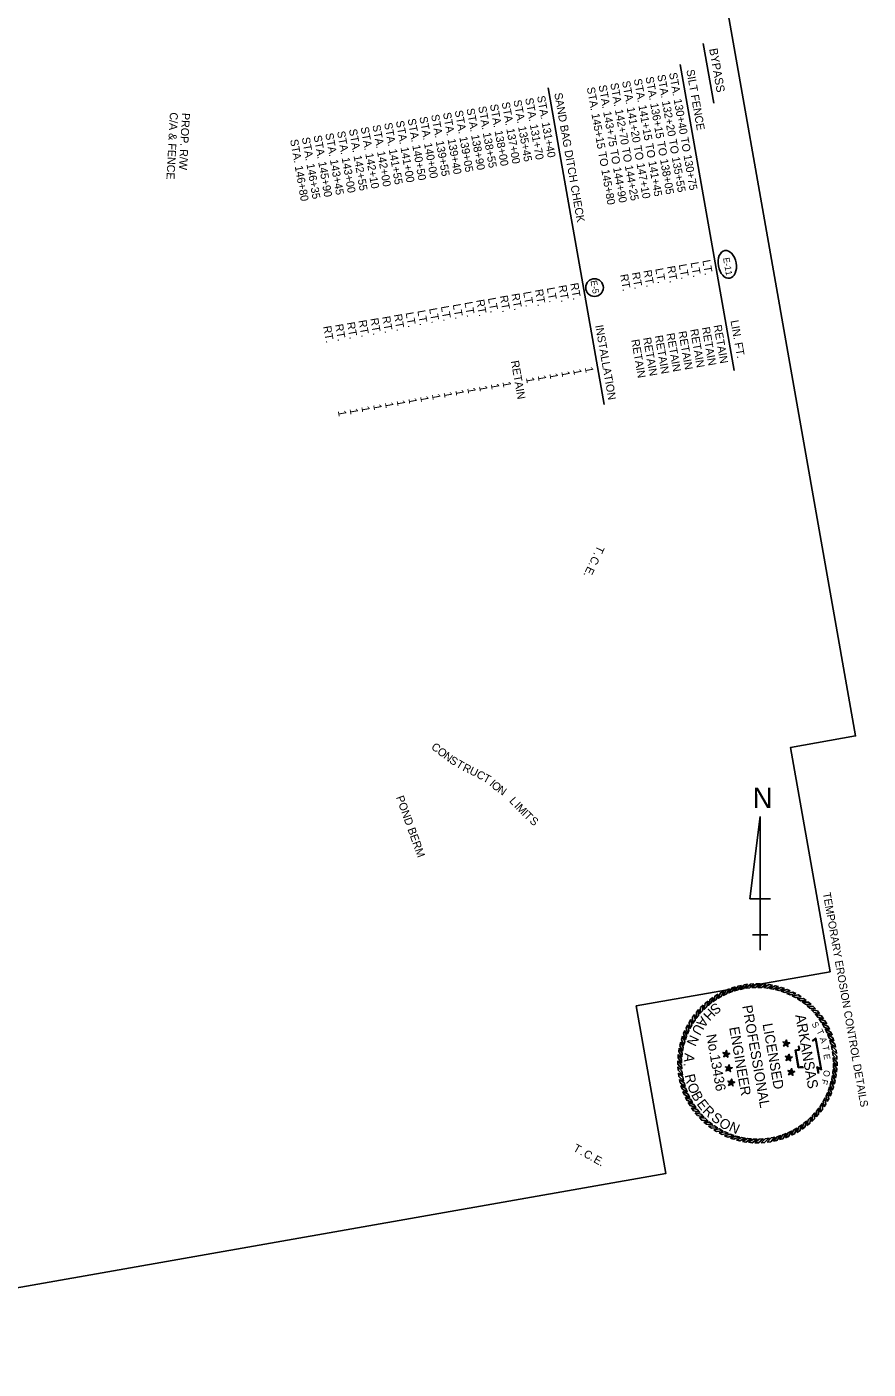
# Model space of a CAD drawing. Extents: x 979945 to 981206, y 1838799 to 1840551.
# Drawn here: x 980575 to 981206, y 1838799 to 1839805 of the extents above; entities that cross this region are included whole.
import ezdxf

# ---------------------------------------------------------------- set-up
doc = ezdxf.new("R2010")
doc.units = 0
for name, color, linetype in [('1', 7, 'Continuous'), ('44', 7, 'Continuous'), ('63', 7, 'Continuous'), ('Default', 7, 'Continuous'), ('G-ANNO-SYMB', 7, 'Continuous'), ('R_Draft', 7, 'Continuous')]:
    doc.layers.add(name, color=color, linetype=linetype)

msp = doc.modelspace()

# ---------------------------------------------------------------- linework, layer by layer
at = {"layer": '1'}
msp.add_circle((981000.5, 1839609.8), 6.61, dxfattribs=at)
msp.add_ellipse((981100, 1839627.2), major_axis=(1.8, -10.4), ratio=0.638788, dxfattribs=at)
at = {"layer": '44'}
for p, q in [((981081.9, 1839792.9), (981089.8, 1839748)), ((981064.8, 1839777), (981105.2, 1839547.7)), ((980965.8, 1839759.5), (981007.6, 1839522.2))]:
    msp.add_line(p, q, dxfattribs=at)
at = {"layer": '63'}
for p, q in [((981124.6, 1839213.1), (981116.9, 1839151.5)), ((981124.6, 1839113.1), (981124.6, 1839213.1)), ((981124.6, 1839213.1), (981124.6, 1839136.2)), ((981116.9, 1839151.5), (981132.3, 1839151.5)), ((981124.6, 1839113.1), (981124.6, 1839136.2)), ((981124.6, 1839124.6), (981118.8, 1839124.6)), ((981118.8, 1839124.6), (981130.4, 1839124.6)), ((981124.6, 1839113.1), (981124.6, 1839124.6))]:
    msp.add_line(p, q, dxfattribs=at)
at = {"layer": 'Default'}
msp.add_lwpolyline([(979944.5, 1840369.9), (980971, 1840550.9), (981196.2, 1839273.6), (981147.4, 1839265), (981177.1, 1839096.8), (981031.8, 1839071.2), (981054, 1838945.6), (980221.5, 1838798.8)], close=True, dxfattribs=at)
at = {"layer": 'G-ANNO-SYMB'}
for points in [[(981101.6, 1839084), (981099.2, 1839083), (981097, 1839079), (981099.5, 1839080.2)], [(981106.1, 1839085.5), (981103.6, 1839084.7), (981101.1, 1839080.9), (981103.7, 1839081.9)], [(981110.6, 1839086.6), (981108.1, 1839086), (981105.3, 1839082.4), (981108, 1839083.2)], [(981115.2, 1839087.4), (981112.7, 1839087), (981109.6, 1839083.6), (981112.3, 1839084.2)], [(981119.9, 1839087.8), (981117.3, 1839087.6), (981114, 1839084.4), (981116.8, 1839084.8)], [(981124.6, 1839087.8), (981122, 1839087.8), (981118.5, 1839084.9), (981121.2, 1839085.1)], [(981129.2, 1839087.5), (981126.7, 1839087.7), (981122.9, 1839085.1), (981125.7, 1839085)], [(981133.9, 1839086.7), (981131.3, 1839087.2), (981127.4, 1839084.9), (981130.1, 1839084.6)], [(981138.4, 1839085.7), (981135.9, 1839086.3), (981131.8, 1839084.3), (981134.5, 1839083.8)], [(981142.9, 1839084.3), (981140.5, 1839085.1), (981136.2, 1839083.5), (981138.9, 1839082.7)], [(981147.2, 1839082.5), (981144.9, 1839083.5), (981140.5, 1839082.2), (981143.1, 1839081.3)], [(981085.4, 1839074.8), (981083.4, 1839073.1), (981082.6, 1839068.6), (981084.6, 1839070.5)], [(981089.2, 1839077.5), (981087.1, 1839076.1), (981085.9, 1839071.6), (981088, 1839073.4)], [(981093.1, 1839080), (981090.9, 1839078.7), (981089.4, 1839074.4), (981091.7, 1839075.9)], [(981097.3, 1839082.2), (981095, 1839081), (981093.1, 1839076.9), (981095.5, 1839078.2)], [(981151.4, 1839080.4), (981149.2, 1839081.6), (981144.7, 1839080.6), (981147.2, 1839079.5)], [(981155.4, 1839078), (981153.3, 1839079.4), (981148.7, 1839078.8), (981151.2, 1839077.4)], [(981159.2, 1839075.3), (981157.2, 1839076.8), (981152.6, 1839076.6), (981154.9, 1839075)], [(981162.8, 1839072.2), (981160.9, 1839073.9), (981156.3, 1839074), (981158.5, 1839072.4)], [(981075.5, 1839064.8), (981074, 1839062.7), (981074.2, 1839058.2), (981075.8, 1839060.5)], [(981078.5, 1839068.4), (981076.9, 1839066.4), (981076.7, 1839061.9), (981078.4, 1839064)], [(981081.8, 1839071.7), (981080, 1839069.9), (981079.5, 1839065.4), (981081.4, 1839067.4)], [(981166.2, 1839069), (981164.4, 1839070.8), (981159.8, 1839071.3), (981161.9, 1839069.4)], [(981169.2, 1839065.4), (981167.6, 1839067.4), (981163.1, 1839068.2), (981165, 1839066.2)], [(981172, 1839061.6), (981170.5, 1839063.7), (981166.1, 1839064.9), (981167.8, 1839062.8)], [(981068.3, 1839052.8), (981067.3, 1839050.4), (981068.6, 1839046), (981069.5, 1839048.6)], [(981070.4, 1839057), (981069.2, 1839054.7), (981070.1, 1839050.2), (981071.3, 1839052.7)], [(981072.8, 1839061), (981071.4, 1839058.8), (981072, 1839054.3), (981073.4, 1839056.7)], [(981174.5, 1839057.7), (981173.2, 1839059.9), (981168.9, 1839061.4), (981170.4, 1839059.1)], [(981176.6, 1839053.5), (981175.5, 1839055.8), (981171.3, 1839057.7), (981172.7, 1839055.3)], [(981178.5, 1839049.2), (981177.5, 1839051.6), (981173.5, 1839053.7), (981174.7, 1839051.2)], [(981065.1, 1839044), (981064.5, 1839041.5), (981066.4, 1839037.3), (981067, 1839040.1)], [(981066.5, 1839048.4), (981065.7, 1839046), (981067.3, 1839041.7), (981068.1, 1839044.4)], [(981144.1, 1839043), (981143.6, 1839043.9), (981141.7, 1839044.2), (981143.1, 1839042.8)], [(981144.1, 1839043), (981143.1, 1839042.8), (981142.2, 1839041.1), (981144, 1839042)], [(981144.1, 1839043), (981144.9, 1839043.8), (981144.5, 1839045.7), (981143.6, 1839043.9)], [(981144.1, 1839043), (981144, 1839042), (981145.4, 1839040.6), (981145.1, 1839042.6)], [(981144.1, 1839043), (981145.1, 1839042.6), (981146.8, 1839043.5), (981144.9, 1839043.8)], [(981179.9, 1839044.7), (981179.2, 1839047.2), (981175.3, 1839049.7), (981176.3, 1839047.1)], [(981181.1, 1839040.2), (981180.5, 1839042.7), (981176.9, 1839045.5), (981177.6, 1839042.8)], [(981063.3, 1839034.8), (981063.1, 1839032.2), (981065.7, 1839028.4), (981065.8, 1839031.2)], [(981064, 1839039.4), (981063.6, 1839036.9), (981065.9, 1839032.9), (981066.2, 1839035.7)], [(981099.1, 1839035.1), (981098.7, 1839036), (981096.7, 1839036.3), (981098.1, 1839034.9)], [(981099.1, 1839035.1), (981098.1, 1839034.9), (981097.3, 1839033.1), (981099, 1839034.1)], [(981099.1, 1839035.1), (981099.9, 1839035.8), (981099.5, 1839037.8), (981098.7, 1839036)], [(981099.1, 1839035.1), (981099, 1839034.1), (981100.4, 1839032.7), (981100.1, 1839034.6)], [(981099.1, 1839035.1), (981100.1, 1839034.6), (981101.8, 1839035.6), (981099.9, 1839035.8)], [(981146, 1839032.3), (981145.5, 1839033.2), (981143.6, 1839033.5), (981145, 1839032.1)], [(981146, 1839032.3), (981145, 1839032.1), (981144.1, 1839030.3), (981145.9, 1839031.3)], [(981146, 1839032.3), (981146.8, 1839033), (981146.4, 1839035), (981145.5, 1839033.2)], [(981146, 1839032.3), (981145.9, 1839031.3), (981147.3, 1839029.9), (981147, 1839031.8)], [(981146, 1839032.3), (981147, 1839031.8), (981148.7, 1839032.8), (981146.8, 1839033)], [(981181.8, 1839035.6), (981181.5, 1839038.1), (981178.1, 1839041.2), (981178.6, 1839038.5)], [(981182.2, 1839030.9), (981182.1, 1839033.5), (981178.9, 1839036.8), (981179.3, 1839034)], [(981182.3, 1839026.2), (981182.3, 1839028.8), (981179.4, 1839032.3), (981179.5, 1839029.6)], [(981063, 1839030.1), (981063, 1839027.5), (981065.9, 1839024), (981065.7, 1839026.7)], [(981063, 1839025.4), (981063.2, 1839022.9), (981066.4, 1839019.5), (981066, 1839022.3)], [(981101, 1839024.4), (981100.6, 1839025.3), (981098.6, 1839025.5), (981100, 1839024.2)], [(981101, 1839024.4), (981100, 1839024.2), (981099.1, 1839022.4), (981100.9, 1839023.3)], [(981101, 1839024.4), (981101.8, 1839025.1), (981101.4, 1839027.1), (981100.6, 1839025.3)], [(981101, 1839024.4), (981100.9, 1839023.3), (981102.3, 1839021.9), (981102, 1839023.9)], [(981101, 1839024.4), (981102, 1839023.9), (981103.7, 1839024.8), (981101.8, 1839025.1)], [(981147.9, 1839021.5), (981147.4, 1839022.5), (981145.5, 1839022.7), (981146.9, 1839021.4)], [(981147.9, 1839021.5), (981148.6, 1839022.3), (981148.3, 1839024.2), (981147.4, 1839022.5)], [(981147.9, 1839021.5), (981148.9, 1839021.1), (981150.6, 1839022), (981148.6, 1839022.3)], [(981181.2, 1839016.9), (981181.7, 1839019.4), (981179.4, 1839023.4), (981179.1, 1839020.7)], [(981181.9, 1839021.5), (981182.2, 1839024.1), (981179.6, 1839027.9), (981179.5, 1839025.1)], [(981063.4, 1839020.7), (981063.8, 1839018.2), (981067.2, 1839015.1), (981066.6, 1839017.9)], [(981064.2, 1839016.1), (981064.8, 1839013.6), (981068.4, 1839010.8), (981067.6, 1839013.5)], [(981102.9, 1839013.6), (981102.4, 1839014.5), (981100.5, 1839014.8), (981101.9, 1839013.4)], [(981102.9, 1839013.6), (981101.9, 1839013.4), (981101, 1839011.6), (981102.8, 1839012.6)], [(981102.9, 1839013.6), (981103.7, 1839014.4), (981103.3, 1839016.3), (981102.4, 1839014.5)], [(981102.9, 1839013.6), (981102.8, 1839012.6), (981104.2, 1839011.2), (981103.9, 1839013.2)], [(981102.9, 1839013.6), (981103.9, 1839013.2), (981105.6, 1839014.1), (981103.7, 1839014.4)], [(981147.9, 1839021.5), (981146.9, 1839021.4), (981146, 1839019.6), (981147.8, 1839020.5)], [(981147.9, 1839021.5), (981147.8, 1839020.5), (981149.2, 1839019.1), (981148.9, 1839021.1)], [(981178.7, 1839007.9), (981179.6, 1839010.3), (981177.9, 1839014.6), (981177.2, 1839011.9)], [(981180.2, 1839012.4), (981180.8, 1839014.8), (981178.8, 1839019), (981178.3, 1839016.2)], [(981065.3, 1839011.6), (981066.1, 1839009.1), (981069.9, 1839006.6), (981068.9, 1839009.2)], [(981066.8, 1839007.1), (981067.8, 1839004.8), (981071.8, 1839002.6), (981070.6, 1839005.1)], [(981068.6, 1839002.8), (981069.8, 1839000.5), (981073.9, 1838998.7), (981072.6, 1839001.1)], [(981172.5, 1838995.4), (981173.8, 1838997.5), (981173.2, 1839002.1), (981171.9, 1838999.6)], [(981174.9, 1838999.4), (981176.1, 1839001.6), (981175.1, 1839006.1), (981174, 1839003.6)], [(981177, 1839003.5), (981178, 1839005.9), (981176.7, 1839010.3), (981175.8, 1839007.7)], [(981070.8, 1838998.7), (981072.1, 1838996.5), (981076.4, 1838994.9), (981074.8, 1838997.2)], [(981073.3, 1838994.7), (981074.7, 1838992.6), (981079.2, 1838991.4), (981077.4, 1838993.6)], [(981166.7, 1838988), (981168.4, 1838989.9), (981168.5, 1838994.5), (981166.8, 1838992.3)], [(981169.7, 1838991.5), (981171.3, 1838993.6), (981171, 1838998.2), (981169.5, 1838995.8)], [(981076, 1838990.9), (981077.7, 1838988.9), (981082.2, 1838988.1), (981080.3, 1838990.1)], [(981079.1, 1838987.4), (981080.9, 1838985.5), (981085.4, 1838985.1), (981083.4, 1838986.9)], [(981082.4, 1838984.1), (981084.4, 1838982.4), (981088.9, 1838982.3), (981086.7, 1838984)], [(981152.1, 1838976.3), (981154.3, 1838977.6), (981155.9, 1838981.9), (981153.6, 1838980.4)], [(981156.1, 1838978.8), (981158.2, 1838980.3), (981159.4, 1838984.7), (981157.2, 1838982.9)], [(981159.9, 1838981.6), (981161.9, 1838983.2), (981162.7, 1838987.7), (981160.7, 1838985.8)], [(981163.4, 1838984.6), (981165.3, 1838986.4), (981165.7, 1838991), (981163.9, 1838988.9)], [(981086, 1838981.1), (981088.1, 1838979.5), (981092.6, 1838979.8), (981090.3, 1838981.3)], [(981089.8, 1838978.3), (981092, 1838977), (981096.5, 1838977.6), (981094.1, 1838978.9)], [(981093.8, 1838975.9), (981096.1, 1838974.7), (981100.6, 1838975.7), (981098.1, 1838976.8)], [(981098, 1838973.8), (981100.4, 1838972.8), (981104.8, 1838974.1), (981102.2, 1838975)], [(981102.4, 1838972), (981104.8, 1838971.2), (981109.1, 1838972.9), (981106.4, 1838973.6)], [(981106.8, 1838970.6), (981109.3, 1838970), (981113.4, 1838972), (981110.7, 1838972.5)], [(981111.4, 1838969.6), (981113.9, 1838969.1), (981117.9, 1838971.4), (981115.1, 1838971.7)], [(981125.4, 1838968.6), (981127.9, 1838968.7), (981131.3, 1838971.9), (981128.5, 1838971.5)], [(981130, 1838969), (981132.6, 1838969.3), (981135.6, 1838972.7), (981132.9, 1838972.2)], [(981134.7, 1838969.7), (981137.2, 1838970.3), (981140, 1838973.9), (981137.3, 1838973.1)], [(981139.2, 1838970.9), (981141.7, 1838971.6), (981144.2, 1838975.5), (981141.6, 1838974.5)], [(981143.7, 1838972.3), (981146, 1838973.3), (981148.2, 1838977.3), (981145.7, 1838976.1)], [(981148, 1838974.2), (981150.3, 1838975.3), (981152.1, 1838979.5), (981149.7, 1838978.1)], [(981116, 1838968.9), (981118.6, 1838968.6), (981122.3, 1838971.2), (981119.6, 1838971.3)], [(981120.7, 1838968.5), (981123.3, 1838968.5), (981126.8, 1838971.4), (981124, 1838971.2)]]:
    msp.add_lwpolyline(points, close=True, dxfattribs=at)
for points in [[(981163.6, 1839045.1), (981166.3, 1839047), (981170.5, 1839023.3), (981167.7, 1839024.8), (981168, 1839023.2), (981168.3, 1839021.9), (981168.3, 1839020.5)], [(981163.8, 1839044.8), (981166.1, 1839046.3), (981170, 1839024), (981167.2, 1839025.5), (981167.6, 1839023.2), (981167.9, 1839021.8), (981168, 1839020.5)], [(981157, 1839024.7), (981156.6, 1839025.1), (981156, 1839025.1), (981154.8, 1839025.1), (981153.2, 1839024.8), (981150.8, 1839038), (981153, 1839038.4), (981153.5, 1839038.5), (981153.6, 1839039), (981153.3, 1839040.9), (981153.7, 1839041.3)], [(981157.2, 1839025), (981156.7, 1839025.5), (981156.1, 1839025.5), (981154.7, 1839025.4), (981153.5, 1839025.2), (981151.3, 1839037.7), (981153.1, 1839038), (981153.9, 1839038.1), (981154, 1839039), (981153.7, 1839040.8), (981154, 1839041.1)]]:
    msp.add_lwpolyline(points, dxfattribs=at)

# ---------------------------------------------------------------- texts
at = {"layer": '1'}
for s, height, p in [('E-11', 4.8, (981096.8, 1839631.9)), ('E-5 ', 4.8, (980997.5, 1839614.8)), ('TEMPORARY EROSION CONTROL DETAILS', 5.862, (981171.6, 1839155.8))]:
    msp.add_text(s, height=height, rotation=280, dxfattribs=at).set_placement(p)
at = {"layer": '44'}
for s, height, p in [('BYPASS', 6.25, (981086.4, 1839788.7)), ('STA. 136+15 TO 138+05', 6, (981038.7, 1839767.5)), ('STA. 132+20 TO 135+55', 6, (981047.5, 1839769.1)), ('STA. 130+40 TO 130+75', 6, (981056.3, 1839770.6)), ('SILT FENCE      ', 6, (981069.3, 1839772.9)), ('STA. 145+15 TO 145+80', 6, (980994.7, 1839759.7)), ('STA. 143+75 TO 144+90', 6, (981003.5, 1839761.3)), ('STA. 142+70 TO 144+25', 6, (981012.3, 1839762.8)), ('STA. 141+20 TO 147+10', 6, (981021.1, 1839764.4)), ('STA. 141+15 TO 141+45', 6, (981029.9, 1839766)), ('STA. 138+00', 6, (980922.1, 1839746.9)), ('STA. 137+00', 6, (980930.9, 1839748.5)), ('STA. 135+45', 6, (980939.7, 1839750.1)), ('STA. 131+70', 6, (980948.5, 1839751.6)), ('STA. 131+40', 6, (980957.4, 1839753.2)), ('SAND BAG DITCH CHECK', 6, (980970.3, 1839755.4)), ('STA. 140+00', 6, (980869.2, 1839737.6)), ('STA. 139+55', 6, (980878, 1839739.2)), ('STA. 139+40', 6, (980886.9, 1839740.7)), ('STA. 139+05', 6, (980895.7, 1839742.3)), ('STA. 138+90', 6, (980904.5, 1839743.8)), ('STA. 138+55', 6, (980913.3, 1839745.4)), ('STA. 143+00', 6, (980807.5, 1839726.7)), ('STA. 142+55', 6, (980816.4, 1839728.3)), ('STA. 142+10', 6, (980825.2, 1839729.9)), ('STA. 142+00', 6, (980834, 1839731.4)), ('STA. 141+55', 6, (980842.8, 1839733)), ('STA. 141+00', 6, (980851.6, 1839734.5)), ('STA. 140+50', 6, (980860.4, 1839736.1)), ('STA. 146+80', 6, (980772.3, 1839720.5)), ('STA. 146+35', 6, (980781.1, 1839722.1)), ('STA. 145+90', 6, (980789.9, 1839723.6)), ('STA. 143+45', 6, (980798.7, 1839725.2)), ('RT.', 6, (981054.8, 1839625.6)), ('LT.', 6, (981063.6, 1839627)), ('LT.', 6, (981072.5, 1839628.5)), ('LT.', 6, (981081.3, 1839630.1)), ('RT.', 6, (981019.6, 1839619.4)), ('RT.', 6, (981028.4, 1839620.9)), ('RT.', 6, (981037.2, 1839622.5)), ('LT.', 6, (981046, 1839623.9)), ('LT.', 6, (980947, 1839606.4)), ('RT.', 6, (980955.8, 1839608.1)), ('LT.', 6, (980964.7, 1839609.5)), ('RT.', 6, (980973.4, 1839611.2)), ('RT.', 6, (980982.3, 1839612.8)), ('LT.', 6, (980885.3, 1839595.6)), ('LT.', 6, (980894.2, 1839597.1)), ('LT.', 6, (980903, 1839598.7)), ('RT.', 6, (980911.8, 1839600.4)), ('LT.', 6, (980920.6, 1839601.8)), ('RT.', 6, (980929.4, 1839603.5)), ('RT.', 6, (980938.2, 1839605)), ('RT.', 6, (980832.4, 1839586.5)), ('RT.', 6, (980841.3, 1839587.9)), ('RT.', 6, (980850.1, 1839589.5)), ('LT.', 6, (980858.9, 1839590.9)), ('LT.', 6, (980867.7, 1839592.4)), ('LT.', 6, (980876.5, 1839594)), ('RT.', 6, (980797.1, 1839580.6)), ('RT.', 6, (980806, 1839582)), ('RT.', 6, (980814.8, 1839583.5)), ('RT.', 6, (980823.6, 1839585)), ('INSTALLATION', 6, (981001, 1839581.3)), ('RETAIN', 6, (981054.4, 1839575.2)), ('RETAIN', 6, (981063.3, 1839576.7)), ('RETAIN', 6, (981072.1, 1839578.3)), ('RETAIN', 6, (981080.9, 1839579.8)), ('RETAIN', 6, (981089.7, 1839581.4)), ('LIN. FT.', 6, (981102.4, 1839584.9)), ('RETAIN', 6, (981028, 1839570.5)), ('RETAIN', 6, (981036.8, 1839572)), ('RETAIN', 6, (981045.6, 1839573.6)), ('RETAIN', 6, (980937.8, 1839554.6)), ('1', 6, (980966.7, 1839545.2)), ('1', 6, (980975.6, 1839546.8)), ('1', 6, (980984.4, 1839548.3)), ('1', 6, (980993.2, 1839549.9)), ('1', 6, (980913.9, 1839535.9)), ('1', 6, (980922.7, 1839537.5)), ('1', 6, (980931.5, 1839539)), ('1', 6, (980949.1, 1839542.1)), ('1', 6, (980957.9, 1839543.7)), ('1', 6, (980861, 1839526.6)), ('1', 6, (980869.8, 1839528.1)), ('1', 6, (980878.6, 1839529.7)), ('1', 6, (980887.4, 1839531.2)), ('1', 6, (980896.2, 1839532.8)), ('1', 6, (980905.1, 1839534.4)), ('1', 6, (980808.1, 1839517.3)), ('1', 6, (980816.9, 1839518.8)), ('1', 6, (980825.7, 1839520.4)), ('1', 6, (980834.6, 1839521.9)), ('1', 6, (980843.4, 1839523.5)), ('1', 6, (980852.2, 1839525))]:
    msp.add_text(s, height=height, rotation=280, dxfattribs=at).set_placement(p)
at = {"layer": '63'}
msp.add_text('N', height=15.4, rotation=0, dxfattribs=at).set_placement((981119, 1839219.5))
at = {"layer": 'G-ANNO-SYMB'}
for s, height, rotation, p in [('S', 7.5, 218.1636, (981091.6, 1839074.1)), ('A', 7.5, 233.4472, (981080.5, 1839063.9)), ('H', 7.5, 225.619, (981086.4, 1839069.8)), ('PROFESSIONAL', 7.5, 280, (981111.2, 1839071.1)), ('ARKANSAS', 7.75, 280, (981150.9, 1839064.2)), ('U', 7.5, 240.9026, (981076.5, 1839058.4)), ('ENGINEER', 7.5, 280, (981101.4, 1839054.9)), ('LICENSED', 7.5, 280, (981126.4, 1839057.5)), ('S', 4.75, 299.7726, (981163, 1839057.7)), ('T', 4.75, 296.9015, (981166.7, 1839052.2)), ('N', 7.5, 244.9326, (981072.3, 1839050)), ('No.13436', 7.47, 280, (981084.2, 1839049.4)), ('A', 4.75, 288.6788, (981169.2, 1839046.8)), ('A', 7.5, 263.0991, (981068.2, 1839036)), ('T', 4.75, 281.4789, (981171.2, 1839040.9)), ('E', 4.75, 276.672, (981172.1, 1839034.9)), ('.', 7.5, 271.3, (981067.3, 1839028.4)), ('O', 4.75, 261.2218, (981172.5, 1839023.3)), ('R', 7.5, 283.2287, (981068, 1839019.2)), ('O', 7.5, 291.4296, (981069.8, 1839011.7)), ('F', 4.75, 255.3628, (981171.1, 1839016.6)), ('B', 7.5, 298.885, (981072.7, 1839004.6)), ('E', 7.5, 307.8315, (981076.7, 1838997.6)), ('R', 7.5, 315.6597, (981081, 1838991.9)), ('S', 7.5, 323.4878, (981087.3, 1838986)), ('O', 7.5, 324.7757, (981093, 1838981.8)), ('N', 7.5, 336.1007, (981100.6, 1838977.8))]:
    msp.add_text(s, height=height, rotation=rotation, dxfattribs=at).set_placement(p)
at = {"layer": 'R_Draft'}
for s, rotation, p in [('C/A & FENCE', 266.993, (980682.3, 1839741.3)), ('PROP. R/W', 266.993, (980691.3, 1839740.9)), ('T', 244.5014, (981002.8, 1839416.9)), ('C', 244.5014, (980999.1, 1839409)), ('.', 244.5014, (981000.3, 1839411.6)), ('.', 244.5014, (980993, 1839396.3)), ('E', 244.5014, (980995.4, 1839401.2)), ('.', 244.5014, (980996.6, 1839403.9)), ('C', 323.021, (980877.6, 1839264.3)), ('O', 323.021, (980882.1, 1839260.8)), ('N', 323.1766, (980886.8, 1839257.3)), ('S', 328.991, (980891.2, 1839253.8)), ('T', 328.991, (980896.1, 1839250.9)), ('R', 334.2867, (980901.1, 1839247.9)), ('U', 334.2867, (980906.2, 1839245.4)), ('C', 331.885, (980911.4, 1839242.9)), ('T', 331.885, (980916.4, 1839240.2)), ('I', 318.5569, (980921.3, 1839237)), ('O', 318.5569, (980922.7, 1839235.7)), ('N', 325.2797, (980927.2, 1839231.9)), ('POND BERM', 289.8211, (980851.6, 1839227.6)), ('L', 312.2725, (980936.2, 1839224.6)), ('I', 313.6073, (980939.9, 1839220.7)), ('M', 313.6073, (980941.3, 1839219.2)), ('I', 314.5987, (980945.7, 1839214.6)), ('T', 314.5987, (980947.1, 1839213.2)), ('S', 320.7675, (980951.3, 1839209.1)), ('T', 330.9256, (980984, 1838962.8)), ('C', 330.9256, (980991.7, 1838958.5)), ('.', 330.9256, (980989.2, 1838959.9)), ('.', 330.9256, (980996.7, 1838955.8)), ('E', 330.9256, (980999.2, 1838954.3)), ('.', 330.9256, (981003.9, 1838951.7))]:
    msp.add_text(s, height=6, rotation=rotation, dxfattribs=at).set_placement(p)

doc.saveas('drawing.dxf')
